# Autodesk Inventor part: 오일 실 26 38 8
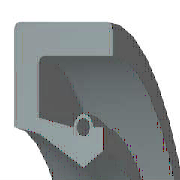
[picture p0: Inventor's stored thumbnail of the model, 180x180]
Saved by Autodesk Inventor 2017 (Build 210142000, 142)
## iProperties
IsCustomPart: 1
Created: 2012-02
Part Number: 오일 실 26 38 8
Material: 고무
Description: 오일-실
Document SubType Name: Modeling
Standard: KS B 2804
Designer: mduedu
Standards Organization: KS
Language: ko-KR
Size Designation: S - 26 38 8
Categories: <MemberInstance><Categories><Category DisplayName="샤프트 부품" InternalName="7f7aeb1f-a693-4053-b835-cee3144e0d98" Mnemonic="SHFT"><Category DisplayName="실링" Intern
Density: 0.93 g/cm^3
Appearance: Rubber - Black - Version 1.1
Author: mduedu
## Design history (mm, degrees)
revolve "본체" stored, may be unused: angle "d17" = 90 deg
revolve "스프링1" stored, may be unused: angle "d18" = 90 deg
body "Solid1"
sketch "스케치1"
  geometry: L1 (0, 19)-(8, 19); L2 (8, 19)-(8, 17.75); L3 (8, 17.75)-(1.75, 17.75); L4 (0, 19)-(0, 15.1); L5 (0, 15.1)-(1.75, 14.75); L6 (1.75, 14.75)-(4.9, 13); L7 (4.9, 13)-(0, 13); L8 (6.3, 13.875)-(6.3, 15.1); L9 (0, 0)-(9.586, 0) reference; L10 (4.9, 13)-(6.3, 13.875); L11 (0, 18)-(0, -3) reference; L12 (-1.917, 0)-(11.503, 0) reference; L13 (4.2, 15.1)-(1.75, 15.59); L14 (1.75, 15.59)-(1.75, 17.75); L15 (6.3, 15.1)-(5.6, 15.1); C1 r 0.455 at (4.9, 15.1); A1 r 0.7 centre (4.9, 15.1) between (5.6, 15.1) and (4.2, 15.1)
  constraints: 26 end point, 5 horizontal alignment, 4 perpendicular, 2 centre point, 2 collinear, 2 horizontal, 2 parallel, 2 point on circle, 2 point on line, 2 vertical alignment, 1 coincident
  dimensions: "d0" = 38 diameter of L1 L9 (= SD2); "d1" = 27.75 diameter of L8.start L9 (= ABDM); "d2" = 1.25 distance of L1.end L2.end (computed from SD); "d3" = 0.91 diameter of C1 (= SPDI); "d4" = 1.4 diameter of A1 (= SPDA); "d5" = 26 diameter of L6.end L9 (= NND); "d6" = 29.5 diameter of L5.end L9 (= TKDM); "d7" = 30.2 diameter of L4.end L9 (= HLDM); "d8" = 4.9 distance from line of C1.centre L4 (= SPDST); "d9" = 6.3 distance between parallel lines of L8 L4 (= SDI); "d10" = 8 distance between parallel lines of L2 L4 (= SWDT); "d12" = 1.75 distance between parallel lines of L14 L4 (= SD)
fillet "모깎기1" dims "d11" = 0.3 (= RR)
other parameters: "SD2" = 38 [user parameter; used in 1 equation term], "SWDT" = 8 [user parameter; used in 1 equation term], "RR" = 0.3 [user parameter; used in 1 equation term], "SD" = 1.75 [user parameter; used in 2 equation terms], "NND" = 26 [user parameter; used in 1 equation term], "SPDA" = 1.4 [user parameter; used in 1 equation term], "SPDI" = 0.91 [user parameter; used in 1 equation term], "TKDM" = 29.5 [user parameter; used in 1 equation term], "HLDM" = 30.2 [user parameter; used in 1 equation term], "ABDM" = 27.75 [user parameter; used in 1 equation term], "SDI" = 6.3 [user parameter; used in 1 equation term], "SPDST" = 4.9 [user parameter; used in 1 equation term], "d13" = 0, "d14" = 0, "d15" = 0, "LAB" = 0.35 [user parameter]
